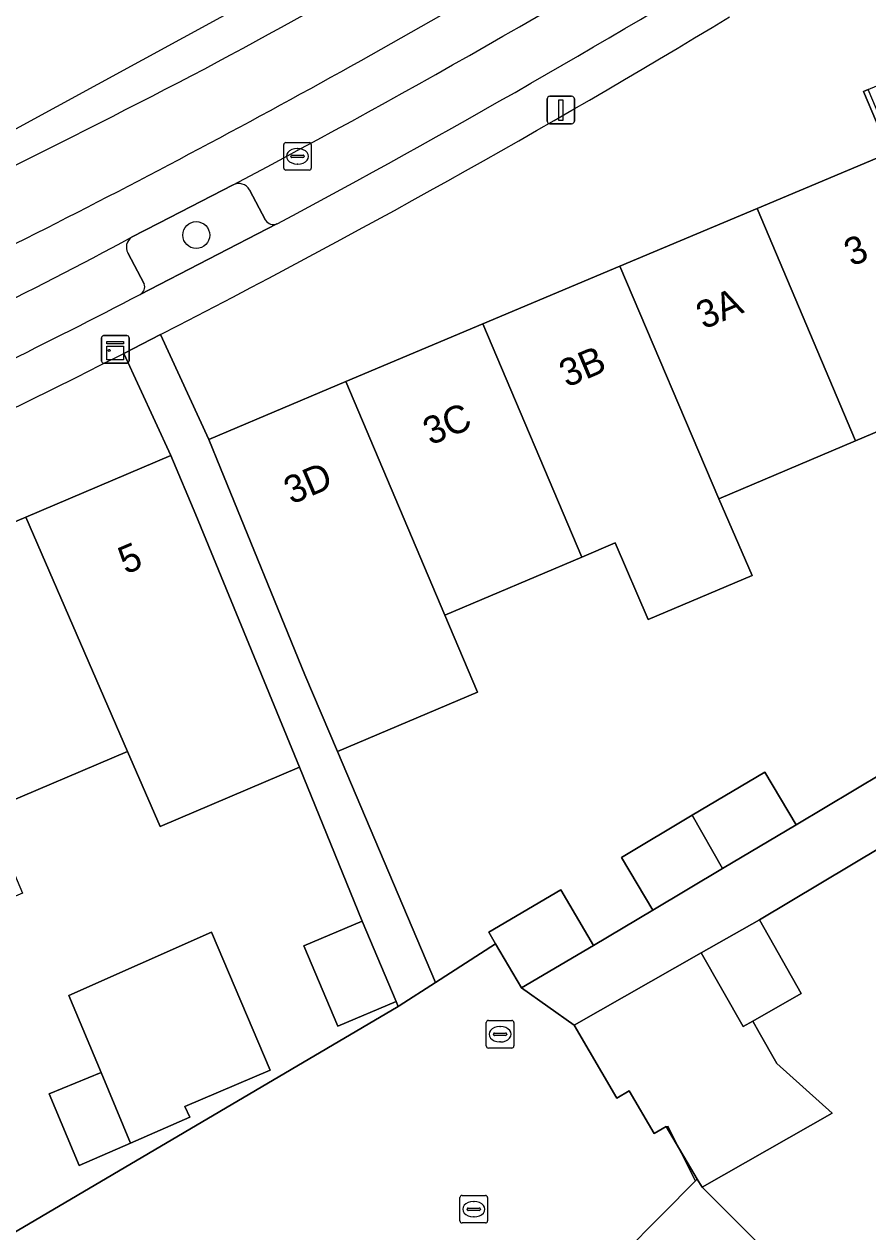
# Model space of a CAD drawing. Extents: x 159960 to 160866, y 382700 to 383354.
# Drawn here: x 160235.05 to 160265.69, y 383279.21 to 383323.04 of the extents above; entities that cross this region are included whole.
import ezdxf

# ---------------------------------------------------------------- set-up
doc = ezdxf.new("R2010")
doc.units = 0
for name, color, linetype in [('IMGEO_Boom', 7, 'Continuous'), ('IMGEO_Erf', 7, 'Continuous'), ('IMGEO_Groenvoorziening', 7, 'Continuous'), ('IMGEO_Kast', 7, 'Continuous'), ('IMGEO_Kolk', 7, 'Continuous'), ('IMGEO_Lichtmast', 7, 'Continuous'), ('IMGEO_Muur', 7, 'Continuous'), ('IMGEO_Pand', 7, 'Continuous'), ('IMGEO_Pand_nummerreeks', 7, 'Continuous'), ('IMGEO_Parkeervlak_open', 7, 'Continuous'), ('IMGEO_Rijbaan_lokaal_gesloten', 7, 'Continuous'), ('IMGEO_Rijbaan_lokaal_open', 7, 'Continuous'), ('IMGEO_Rioolput', 7, 'Continuous'), ('IMGEO_Voetpad_open', 7, 'Continuous')]:
    doc.layers.add(name, color=color, linetype=linetype)

msp = doc.modelspace()

# ---------------------------------------------------------------- linework, layer by layer
at = {"layer": 'IMGEO_Boom'}
msp.add_circle((160241.302, 383315.385), 0.489, dxfattribs=at)
at = {"layer": 'IMGEO_Erf'}
for points in [[(160240.009, 383311.773), (160241.764, 383307.97), (160243.813, 383308.84), (160246.739, 383310.072), (160251.715, 383312.166), (160256.692, 383314.26), (160261.671, 383316.356), (160266.474, 383318.377), (160265.532, 383320.596), (160265.706, 383320.67), (160270.677, 383322.78)], [(160214.587, 383299.042), (160215.507, 383296.848), (160220.224, 383298.848), (160225.159, 383300.94), (160226.065, 383301.324), (160230.264, 383303.101), (160235.111, 383305.152), (160240.381, 383307.382), (160238.674, 383311.092)], [(160270.218, 383310.027), (160265.248, 383307.917), (160260.277, 383305.807), (160261.487, 383303.031), (160257.71, 383301.427), (160256.519, 383304.212), (160255.306, 383303.697), (160250.336, 383301.587), (160251.514, 383298.796), (160246.434, 383296.639), (160249.994, 383288.259), (160252.176, 383289.663), (160251.926, 383290.089), (160254.541, 383291.625), (160255.731, 383289.599), (160257.885, 383290.883), (160256.746, 383292.793), (160259.315, 383294.324), (160261.946, 383295.893), (160263.085, 383293.983), (160267.305, 383296.498)], [(160248.64, 383287.39), (160248.565, 383287.568), (160246.45, 383286.67), (160245.213, 383289.586), (160247.327, 383290.483), (160245.053, 383296.067), (160239.989, 383293.918), (160238.806, 383296.644), (160233.849, 383294.539), (160233.726, 383294.487), (160234.996, 383291.495), (160229.965, 383289.36), (160229.529, 383290.396), (160224.599, 383288.303), (160223.785, 383290.268), (160218.916, 383288.201), (160219.215, 383287.481), (160214.195, 383285.435)], [(160266.216, 383293.194), (160261.754, 383290.535), (160263.274, 383287.861), (160261.51, 383286.857), (160261.743, 383286.447), (160262.389, 383285.314), (160264.398, 383283.518), (160259.67, 383280.828), (160261.621, 383278.874), (160263.551, 383276.941), (160259.686, 383272.913), (160257.707, 383274.874), (160256.335, 383273.504), (160254.138, 383275.705), (160251.785, 383273.342), (160260.491, 383264.497), (160264.32, 383268.32), (160268.247, 383272.242)], [(160231.792, 383277.479), (160248.64, 383287.39)]]:
    msp.add_lwpolyline(points, dxfattribs=at)
msp.add_lwpolyline([(160241.861, 383290.081), (160243.991, 383285.075), (160240.89, 383283.755), (160241.071, 383283.365), (160238.921, 383282.427), (160237.054, 383281.613), (160235.963, 383284.219), (160237.848, 383284.989), (160236.68, 383287.779)], close=True, dxfattribs=at)
for centre, radius, start, end in [((160085.395, 383613.072), 338.654, 297.16494, 301.16911), ((160085.227, 383613.347), 338.975, 286.55987, 296.91566)]:
    msp.add_arc(centre, radius, start, end, dxfattribs=at)
at = {"layer": 'IMGEO_Groenvoorziening'}
for points in [[(160242.639, 383317.207), (160239.943, 383315.821), (160238.953, 383315.306)], [(160243.824, 383315.928), (160243.243, 383317.029)], [(160239.267, 383313.229), (160244.236, 383315.791)], [(160238.817, 383314.741), (160239.415, 383313.619)]]:
    msp.add_lwpolyline(points, dxfattribs=at)
for centre, radius, start, end in [((160242.848, 383316.801), 0.456, 29.9697, 117.1896), ((160244.115, 383316.116), 0.347, 212.8446, 290.369), ((160239.195, 383314.949), 0.431, 124.1096, 208.8223), ((160239.112, 383313.511), 0.321, 298.7429, 19.6949)]:
    msp.add_arc(centre, radius, start, end, dxfattribs=at)
at = {"layer": 'IMGEO_Kast'}
for p, q in [((160237.864, 383310.812), (160237.864, 383311.653)), ((160237.864, 383311.653), (160237.864, 383310.812)), ((160237.939, 383311.737), (160238.78, 383311.737)), ((160238.78, 383311.737), (160237.939, 383311.737)), ((160238.864, 383311.662), (160238.864, 383310.821)), ((160238.864, 383310.821), (160238.864, 383311.662)), ((160238.789, 383310.737), (160237.948, 383310.737)), ((160237.948, 383310.737), (160238.789, 383310.737))]:
    msp.add_line(p, q, dxfattribs=at)
for points in [[(160238.059, 383311.527), (160238.659, 383311.527), (160238.659, 383311.442), (160238.059, 383311.442), (160238.059, 383311.527)], [(160238.059, 383311.352), (160238.659, 383311.352), (160238.659, 383310.863), (160238.059, 383310.863), (160238.059, 383311.352)]]:
    msp.add_lwpolyline(points, dxfattribs=at)
msp.add_circle((160238.143, 383311.201), 0.0377, dxfattribs=at)
for centre, start, end in [((160237.942, 383311.659), 92.4484, 184.2845), ((160237.942, 383311.659), 92.4484, 184.2845), ((160238.786, 383311.659), 2.4484, 94.2845), ((160238.786, 383311.659), 2.4484, 94.2845), ((160237.942, 383310.815), 182.4484, 274.2845), ((160237.942, 383310.815), 182.4484, 274.2845), ((160238.786, 383310.815), 272.4484, 4.2845), ((160238.786, 383310.815), 272.4484, 4.2845)]:
    msp.add_arc(centre, 0.0779, start, end, dxfattribs=at)
at = {"layer": 'IMGEO_Kolk'}
for p, q in [((160244.481, 383317.819), (160244.481, 383318.671)), ((160244.556, 383318.745), (160245.408, 383318.745)), ((160245.482, 383318.671), (160245.482, 383317.819)), ((160244.74, 383318.239), (160244.74, 383318.251)), ((160245.178, 383318.202), (160244.78, 383318.202)), ((160244.783, 383318.288), (160245.181, 383318.288)), ((160244.969, 383318.525), (160244.994, 383318.525)), ((160245.224, 383318.251), (160245.224, 383318.239)), ((160245.408, 383317.745), (160244.556, 383317.745)), ((160244.992, 383317.965), (160244.967, 383317.965)), ((160250.881, 383279.601), (160250.881, 383280.453)), ((160250.956, 383280.527), (160251.808, 383280.527)), ((160251.882, 383280.453), (160251.882, 383279.601)), ((160251.14, 383280.021), (160251.14, 383280.033)), ((160251.183, 383280.07), (160251.581, 383280.07)), ((160251.369, 383280.307), (160251.394, 383280.307)), ((160251.624, 383280.033), (160251.624, 383280.021)), ((160251.578, 383279.984), (160251.18, 383279.984)), ((160251.392, 383279.747), (160251.367, 383279.747)), ((160251.808, 383279.527), (160250.956, 383279.527))]:
    msp.add_line(p, q, dxfattribs=at)
for points in [[(160244.481, 383317.819), (160244.481, 383318.671)], [(160244.556, 383318.745), (160245.408, 383318.745)], [(160245.482, 383318.671), (160245.482, 383317.819)], [(160245.408, 383317.745), (160244.556, 383317.745)], [(160250.881, 383279.601), (160250.881, 383280.453)], [(160250.956, 383280.527), (160251.808, 383280.527)], [(160251.882, 383280.453), (160251.882, 383279.601)], [(160251.808, 383279.527), (160250.956, 383279.527)]]:
    msp.add_lwpolyline(points, dxfattribs=at)
for centre, radius, start, end in [((160244.558, 383318.669), 0.0765, 91.552, 178.448), ((160244.558, 383318.669), 0.0765, 91.552, 178.448), ((160245.406, 383318.669), 0.0765, 1.552, 88.448), ((160245.406, 383318.669), 0.0765, 1.552, 88.448), ((160244.78, 383318.248), 0.0403, 85.8775, 175.7526), ((160244.777, 383318.238), 0.0366, 178.938, 274.7102), ((160245.181, 383318.245), 0.043, 264.8664, 352.4533), ((160245.185, 383318.25), 0.0386, 1.7309, 96.639), ((160244.558, 383317.821), 0.0765, 181.552, 268.448), ((160244.558, 383317.821), 0.0765, 181.552, 268.448), ((160245.406, 383317.821), 0.0765, 271.552, 358.448), ((160245.406, 383317.821), 0.0765, 271.552, 358.448), ((160250.958, 383280.451), 0.0765, 91.552, 178.448), ((160250.958, 383280.451), 0.0765, 91.552, 178.448), ((160251.806, 383280.451), 0.0765, 1.552, 88.448), ((160251.806, 383280.451), 0.0765, 1.552, 88.448), ((160251.18, 383280.03), 0.0403, 85.8775, 175.7526), ((160251.177, 383280.02), 0.0366, 178.938, 274.7102), ((160251.581, 383280.027), 0.043, 264.8664, 352.4533), ((160251.585, 383280.032), 0.0386, 1.7309, 96.639), ((160250.958, 383279.603), 0.0765, 181.552, 268.448), ((160250.958, 383279.603), 0.0765, 181.552, 268.448), ((160251.806, 383279.603), 0.0765, 271.552, 358.448), ((160251.806, 383279.603), 0.0765, 271.552, 358.448)]:
    msp.add_arc(centre, radius, start, end, dxfattribs=at)
for centre, major_axis, ratio, start_param, end_param in [((160244.968, 383318.245), (-0.387, 0.002), 0.722429, 4.712389, 7.853982), ((160244.993, 383318.245), (-0.39, 0.002), 0.717154, 1.570796, 4.712389), ((160251.368, 383280.027), (-0.387, 0.002), 0.722429, 4.712389, 7.853982), ((160251.393, 383280.027), (-0.39, 0.002), 0.717154, 1.570796, 4.712389)]:
    msp.add_ellipse(centre, major_axis=major_axis, ratio=ratio, start_param=start_param, end_param=end_param, dxfattribs=at)
at = {"layer": 'IMGEO_Lichtmast'}
for p, q in [((160254.046, 383319.526), (160254.046, 383320.326)), ((160254.046, 383320.326), (160254.046, 383319.526)), ((160254.146, 383320.426), (160254.936, 383320.426)), ((160254.936, 383320.426), (160254.146, 383320.426)), ((160255.036, 383320.326), (160255.036, 383319.526)), ((160255.036, 383319.526), (160255.036, 383320.326)), ((160254.936, 383319.426), (160254.146, 383319.426)), ((160254.146, 383319.426), (160254.936, 383319.426))]:
    msp.add_line(p, q, dxfattribs=at)
msp.add_lwpolyline([(160254.466, 383320.301), (160254.616, 383320.301), (160254.616, 383319.551), (160254.466, 383319.551), (160254.466, 383320.301)], dxfattribs=at)
for centre, start, end in [((160254.146, 383320.326), 90, 180), ((160254.146, 383320.326), 90, 180), ((160254.936, 383320.326), 0, 90), ((160254.936, 383320.326), 360, 90), ((160254.146, 383319.526), 180, 270), ((160254.146, 383319.526), 180, 270), ((160254.936, 383319.526), 270, 0), ((160254.936, 383319.526), 270, 0)]:
    msp.add_arc(centre, 0.1, start, end, dxfattribs=at)
at = {"layer": 'IMGEO_Muur'}
msp.add_lwpolyline([(160258.422, 383283.057), (160259.424, 383281.075)], dxfattribs=at)
at = {"layer": 'IMGEO_Pand'}
for points in [[(160265.706, 383320.67), (160265.532, 383320.596), (160266.474, 383318.377), (160261.671, 383316.356), (160265.248, 383307.917), (160270.218, 383310.027)], [(160261.671, 383316.356), (160256.692, 383314.26), (160260.277, 383305.807), (160265.248, 383307.917)], [(160256.692, 383314.26), (160251.715, 383312.166), (160255.306, 383303.697), (160256.519, 383304.212), (160257.71, 383301.427), (160261.487, 383303.031), (160260.277, 383305.807)], [(160251.715, 383312.166), (160246.739, 383310.072), (160250.336, 383301.587), (160255.306, 383303.697)], [(160246.739, 383310.072), (160243.813, 383308.84), (160241.764, 383307.97), (160242.179, 383306.924), (160245.249, 383299.428), (160246.434, 383296.639), (160251.514, 383298.796), (160250.336, 383301.587)], [(160241.29, 383305.235), (160240.381, 383307.382), (160235.111, 383305.152), (160238.806, 383296.644), (160239.989, 383293.918), (160245.053, 383296.067)], [(160235.111, 383305.152), (160230.264, 383303.101), (160233.849, 383294.539), (160238.806, 383296.644)], [(160263.085, 383293.983), (160261.946, 383295.893), (160259.315, 383294.324), (160260.414, 383292.391)], [(160260.414, 383292.391), (160259.315, 383294.324), (160256.746, 383292.793), (160257.885, 383290.883)], [(160252.176, 383289.663), (160253.115, 383288.063), (160255.731, 383289.599), (160254.541, 383291.625), (160251.926, 383290.089)], [(160261.754, 383290.535), (160259.639, 383289.332), (160261.169, 383286.661), (160261.51, 383286.857), (160263.274, 383287.861)], [(160241.861, 383290.081), (160236.68, 383287.779), (160237.848, 383284.989), (160238.921, 383282.427), (160241.071, 383283.365), (160240.89, 383283.755), (160243.991, 383285.075)], [(160248.565, 383287.568), (160247.327, 383290.483), (160245.213, 383289.586), (160246.45, 383286.67)], [(160262.389, 383285.314), (160261.743, 383286.447), (160261.51, 383286.857), (160261.169, 383286.661), (160259.639, 383289.332), (160255.022, 383286.704), (160256.572, 383284.059), (160257.019, 383284.328), (160257.935, 383282.78), (160258.369, 383283.027), (160259.498, 383281.119), (160259.67, 383280.828), (160264.398, 383283.518)], [(160237.848, 383284.989), (160235.963, 383284.219), (160237.054, 383281.613), (160238.921, 383282.427)], [(160259.67, 383280.828), (160259.498, 383281.119), (160255.486, 383277.074), (160257.707, 383274.874), (160259.686, 383272.913), (160263.551, 383276.941), (160261.621, 383278.874)]]:
    msp.add_lwpolyline(points, close=True, dxfattribs=at)
at = {"layer": 'IMGEO_Parkeervlak_open'}
for points in [[(160243.243, 383317.029), (160243.824, 383315.928)], [(160239.415, 383313.619), (160238.817, 383314.741)]]:
    msp.add_lwpolyline(points, dxfattribs=at)
for centre, radius, start, end in [((160095.99, 383595.123), 314.234, 297.81938, 301.89791), ((160079.355, 383624.312), 349.816, 298.12116, 301.5717), ((160242.848, 383316.801), 0.456, 29.9697, 117.1896), ((160244.115, 383316.116), 0.347, 212.8446, 290.369), ((160156.98, 383467.715), 173.055, 294.08992, 298.27349), ((160239.195, 383314.949), 0.431, 124.1096, 208.8223), ((160239.112, 383313.511), 0.321, 298.7429, 19.6949), ((160121.643, 383539.618), 255.122, 294.90714, 297.45497)]:
    msp.add_arc(centre, radius, start, end, dxfattribs=at)
at = {"layer": 'IMGEO_Rijbaan_lokaal_gesloten'}
for points in [[(160292.227, 383351.338), (160278.765, 383345.555), (160257.736, 383331.761), (160223.911, 383313.333)], [(160238.953, 383315.306), (160239.943, 383315.821), (160242.639, 383317.207)]]:
    msp.add_lwpolyline(points, dxfattribs=at)
for centre, radius, start, end in [((160063.506, 383652.236), 375.714, 298.29792, 300.87085), ((160095.99, 383595.123), 314.234, 297.81938, 301.89791), ((160091.902, 383599.767), 318.516, 295.14274, 299.94982), ((160059.71, 383670.478), 393.611, 295.01345, 297.5257), ((160156.98, 383467.715), 173.055, 294.08992, 298.27349)]:
    msp.add_arc(centre, radius, start, end, dxfattribs=at)
at = {"layer": 'IMGEO_Rijbaan_lokaal_open'}
msp.add_lwpolyline([(160255.486, 383277.074), (160259.498, 383281.119), (160258.369, 383283.027), (160257.935, 383282.78), (160257.019, 383284.328), (160256.572, 383284.059), (160255.022, 383286.704), (160253.115, 383288.063), (160252.176, 383289.663), (160249.994, 383288.259), (160248.677, 383287.412), (160248.64, 383287.39), (160231.792, 383277.479)], dxfattribs=at)
for centre, radius, start, end in [((160063.506, 383652.236), 375.714, 298.29792, 300.87085), ((160091.902, 383599.767), 318.516, 295.14274, 299.94982), ((160059.71, 383670.478), 393.611, 295.01345, 297.5257)]:
    msp.add_arc(centre, radius, start, end, dxfattribs=at)
at = {"layer": 'IMGEO_Rioolput'}
for p, q in [((160251.836, 383285.952), (160251.836, 383286.804)), ((160251.911, 383286.878), (160252.763, 383286.878)), ((160252.324, 383286.658), (160252.349, 383286.658)), ((160252.837, 383286.804), (160252.837, 383285.952)), ((160252.095, 383286.372), (160252.095, 383286.384)), ((160252.533, 383286.335), (160252.135, 383286.335)), ((160252.138, 383286.421), (160252.536, 383286.421)), ((160252.579, 383286.384), (160252.579, 383286.372)), ((160252.763, 383285.878), (160251.911, 383285.878)), ((160252.347, 383286.098), (160252.322, 383286.098))]:
    msp.add_line(p, q, dxfattribs=at)
for points in [[(160251.836, 383285.952), (160251.836, 383286.804)], [(160251.911, 383286.878), (160252.763, 383286.878)], [(160252.837, 383286.804), (160252.837, 383285.952)], [(160252.763, 383285.878), (160251.911, 383285.878)]]:
    msp.add_lwpolyline(points, dxfattribs=at)
for centre, radius, start, end in [((160251.913, 383286.802), 0.0765, 91.552, 178.448), ((160251.913, 383286.802), 0.0765, 91.552, 178.448), ((160252.761, 383286.802), 0.0765, 1.552, 88.448), ((160252.761, 383286.802), 0.0765, 1.552, 88.448), ((160252.135, 383286.381), 0.0403, 85.8775, 175.7526), ((160252.132, 383286.371), 0.0366, 178.938, 274.7102), ((160252.536, 383286.378), 0.043, 264.8664, 352.4533), ((160252.54, 383286.383), 0.0386, 1.7309, 96.639), ((160251.913, 383285.954), 0.0765, 181.552, 268.448), ((160251.913, 383285.954), 0.0765, 181.552, 268.448), ((160252.761, 383285.954), 0.0765, 271.552, 358.448), ((160252.761, 383285.954), 0.0765, 271.552, 358.448)]:
    msp.add_arc(centre, radius, start, end, dxfattribs=at)
for centre, major_axis, ratio, start_param, end_param in [((160252.323, 383286.378), (-0.387, 0.002), 0.722429, 4.712389, 7.853982), ((160252.348, 383286.378), (-0.39, 0.002), 0.717154, 1.570796, 4.712389)]:
    msp.add_ellipse(centre, major_axis=major_axis, ratio=ratio, start_param=start_param, end_param=end_param, dxfattribs=at)
at = {"layer": 'IMGEO_Voetpad_open'}
for points in [[(160244.236, 383315.791), (160239.267, 383313.229)], [(160238.674, 383311.092), (160240.009, 383311.773)], [(160267.305, 383296.498), (160263.085, 383293.983), (160260.414, 383292.391), (160257.885, 383290.883), (160255.731, 383289.599), (160253.115, 383288.063), (160255.022, 383286.704), (160259.639, 383289.332), (160261.754, 383290.535), (160266.216, 383293.194)]]:
    msp.add_lwpolyline(points, dxfattribs=at)
msp.add_lwpolyline([(160242.179, 383306.924), (160241.764, 383307.97), (160240.009, 383311.773), (160238.674, 383311.092), (160240.381, 383307.382), (160241.29, 383305.235), (160245.053, 383296.067), (160247.327, 383290.483), (160248.565, 383287.568), (160248.64, 383287.39), (160248.677, 383287.412), (160249.994, 383288.259), (160246.434, 383296.639), (160245.249, 383299.428)], close=True, dxfattribs=at)
for centre, radius, start, end in [((160079.355, 383624.312), 349.816, 298.12116, 301.5717), ((160085.395, 383613.072), 338.654, 297.16494, 301.16911), ((160121.643, 383539.618), 255.122, 294.90714, 297.45497), ((160085.227, 383613.347), 338.975, 286.55987, 296.91566)]:
    msp.add_arc(centre, radius, start, end, dxfattribs=at)

# ---------------------------------------------------------------- texts
at = {"layer": 'IMGEO_Pand_nummerreeks'}
for s, p in [('3', (160265.104, 383314.232)), ('3A', (160259.731, 383311.952)), ('3B', (160254.76, 383309.842)), ('3C', (160249.813, 383307.742)), ('3D', (160244.759, 383305.597)), ('5', (160238.743, 383303.057))]:
    msp.add_text(s, height=1, rotation=22.9985, dxfattribs=at).set_placement(p)

doc.saveas('drawing.dxf')
